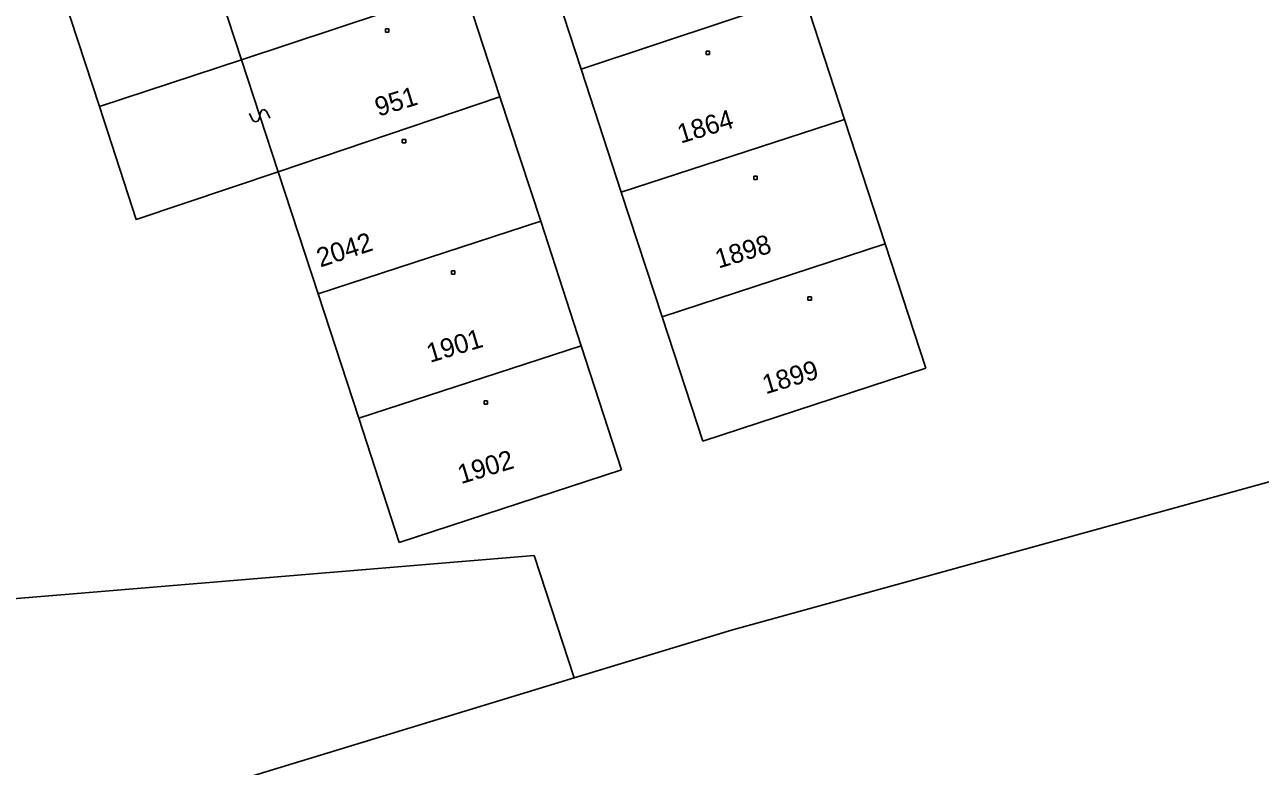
# Model space of a CAD drawing. Extents: x -493352 to -492964, y -1127001 to -1126712.
# Drawn here: x -493269.27 to -493236.25, y -1126768.92 to -1126749.1 of the extents above; entities that cross this region are included whole.
import ezdxf

# ---------------------------------------------------------------- set-up
doc = ezdxf.new("R2010")
doc.units = 0
doc.layers.add('katastrální mapa', color=7, linetype='Continuous')

msp = doc.modelspace()

# ---------------------------------------------------------------- linework, layer by layer
at = {"layer": 'katastrální mapa'}
for p, q in [((-493264.47, -1126746.99), (-493263.48, -1126750.04)), ((-493255.41, -1126747.2), (-493254.4, -1126750.29)), ((-493263.48, -1126750.04), (-493257.54, -1126748.07)), ((-493257.54, -1126748.07), (-493256.57, -1126751.03)), ((-493268.27, -1126748.25), (-493267.27, -1126751.29)), ((-493254.4, -1126750.29), (-493248.45, -1126748.31)), ((-493248.45, -1126748.31), (-493247.36, -1126751.63)), ((-493259.63, -1126749.21), (-493259.54, -1126749.21)), ((-493259.63, -1126749.3), (-493259.63, -1126749.21)), ((-493259.54, -1126749.3), (-493259.63, -1126749.3)), ((-493259.54, -1126749.21), (-493259.54, -1126749.3)), ((-493267.27, -1126751.29), (-493263.48, -1126750.04)), ((-493263.48, -1126750.04), (-493262.5, -1126753.03)), ((-493251.06, -1126749.81), (-493250.97, -1126749.81)), ((-493251.06, -1126749.9), (-493251.06, -1126749.81)), ((-493250.97, -1126749.9), (-493251.06, -1126749.9)), ((-493250.97, -1126749.81), (-493250.97, -1126749.9)), ((-493254.4, -1126750.29), (-493253.33, -1126753.58)), ((-493262.5, -1126753.03), (-493256.57, -1126751.03)), ((-493256.57, -1126751.03), (-493255.48, -1126754.35)), ((-493267.27, -1126751.29), (-493266.29, -1126754.31)), ((-493262.88, -1126751.37), (-493262.94, -1126751.39)), ((-493262.81, -1126751.41), (-493262.88, -1126751.37)), ((-493263.17, -1126751.66), (-493263.26, -1126751.47)), ((-493263.1, -1126751.7), (-493263.17, -1126751.66)), ((-493263.04, -1126751.68), (-493263.1, -1126751.7)), ((-493263, -1126751.6), (-493263.04, -1126751.68)), ((-493262.98, -1126751.47), (-493263, -1126751.6)), ((-493262.94, -1126751.39), (-493262.98, -1126751.47)), ((-493262.72, -1126751.6), (-493262.81, -1126751.41)), ((-493253.33, -1126753.58), (-493247.36, -1126751.63)), ((-493247.36, -1126751.63), (-493246.28, -1126754.96)), ((-493259.18, -1126752.17), (-493259.09, -1126752.17)), ((-493259.18, -1126752.26), (-493259.18, -1126752.17)), ((-493259.09, -1126752.26), (-493259.18, -1126752.26)), ((-493259.09, -1126752.17), (-493259.09, -1126752.26)), ((-493266.29, -1126754.31), (-493262.5, -1126753.03)), ((-493262.5, -1126753.03), (-493261.43, -1126756.29)), ((-493249.79, -1126753.15), (-493249.7, -1126753.15)), ((-493249.79, -1126753.24), (-493249.79, -1126753.15)), ((-493249.7, -1126753.24), (-493249.79, -1126753.24)), ((-493249.7, -1126753.15), (-493249.7, -1126753.24)), ((-493253.33, -1126753.58), (-493252.24, -1126756.91)), ((-493261.43, -1126756.29), (-493255.48, -1126754.35)), ((-493255.48, -1126754.35), (-493254.4, -1126757.68)), ((-493252.24, -1126756.91), (-493246.28, -1126754.96)), ((-493246.28, -1126754.96), (-493245.19, -1126758.28)), ((-493257.87, -1126755.68), (-493257.78, -1126755.68)), ((-493257.87, -1126755.77), (-493257.87, -1126755.68)), ((-493257.78, -1126755.77), (-493257.87, -1126755.77)), ((-493257.78, -1126755.68), (-493257.78, -1126755.77)), ((-493261.43, -1126756.29), (-493260.34, -1126759.62)), ((-493248.34, -1126756.37), (-493248.25, -1126756.37)), ((-493248.34, -1126756.46), (-493248.34, -1126756.37)), ((-493248.25, -1126756.46), (-493248.34, -1126756.46)), ((-493248.25, -1126756.37), (-493248.25, -1126756.46)), ((-493252.24, -1126756.91), (-493251.15, -1126760.23)), ((-493260.34, -1126759.62), (-493254.4, -1126757.68)), ((-493254.4, -1126757.68), (-493253.32, -1126761)), ((-493251.15, -1126760.23), (-493245.19, -1126758.28)), ((-493256.99, -1126759.15), (-493256.9, -1126759.15)), ((-493256.99, -1126759.24), (-493256.99, -1126759.15)), ((-493256.9, -1126759.24), (-493256.99, -1126759.24)), ((-493256.9, -1126759.15), (-493256.9, -1126759.24)), ((-493250.38, -1126765.28), (-493228.16, -1126759.15)), ((-493260.34, -1126759.62), (-493259.26, -1126762.94)), ((-493259.26, -1126762.94), (-493253.32, -1126761)), ((-493275.13, -1126764.9), (-493255.66, -1126763.29)), ((-493255.66, -1126763.29), (-493254.59, -1126766.56)), ((-493254.59, -1126766.56), (-493250.38, -1126765.28)), ((-493281.85, -1126774.85), (-493254.59, -1126766.56))]:
    msp.add_line(p, q, dxfattribs=at)

# ---------------------------------------------------------------- texts
for s, rotation, p in [('951', 17.073, (-493259.82, -1126751.56)), ('1864', 16.785, (-493251.74, -1126752.28)), ('2042', 18, (-493261.37, -1126755.59)), ('1898', 16.785, (-493250.73, -1126755.62)), ('1901', 16.785, (-493258.44, -1126758.14)), ('1899', 16.785, (-493249.47, -1126758.98)), ('1902', 16.785, (-493257.61, -1126761.38))]:
    msp.add_text(s, height=0.51, rotation=rotation, dxfattribs=at).set_placement(p)

doc.saveas('drawing.dxf')
